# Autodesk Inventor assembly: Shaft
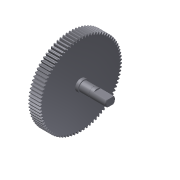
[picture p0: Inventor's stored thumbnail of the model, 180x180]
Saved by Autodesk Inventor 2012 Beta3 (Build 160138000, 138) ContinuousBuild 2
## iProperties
Created: 2010-12
Part Number: Shaft
Document SubType Name: Assembly
Designer: Thom Tremblay
ClientObjectVersion: 1
Author: Thom Tremblay
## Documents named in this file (2)
- C:\Inventor 2012 Essentials\Assemblies\Chapter 6\c6-01\Design Accelerator\Shaft4.iam
- C:\Inventor 2012 Essentials\Assemblies\Chapter 6\c6-01\Design Accelerator\Shaft4.ipt
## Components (1 placed, 1 different names)
1. Shaft:1
